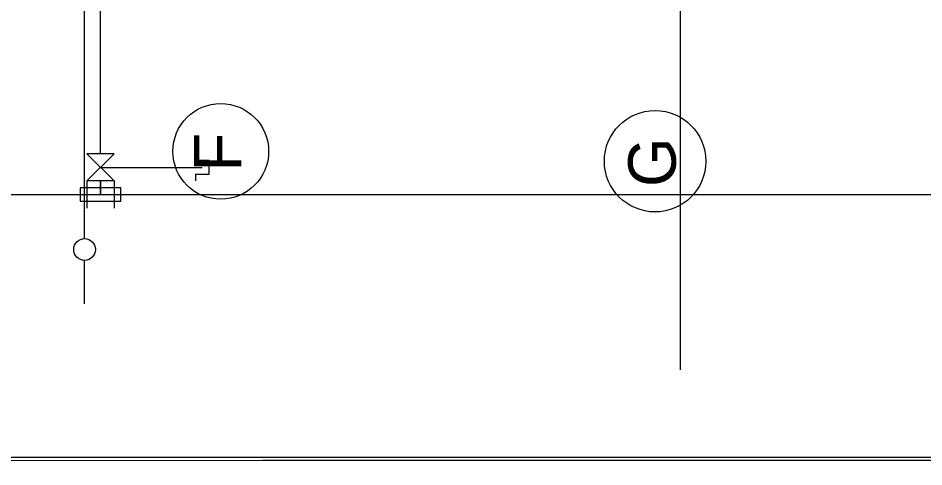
# Model space of a CAD drawing. Extents: x -264205 to -263659, y -1242401 to -1241986.
# Drawn here: x -263888.26 to -263871.58, y -1242255.16 to -1242246.89 of the extents above; entities that cross this region are included whole.
import ezdxf

# ---------------------------------------------------------------- set-up
doc = ezdxf.new("R2010")
doc.units = 0
for name, color, linetype in [('HESCON_OSI_STAVBY_KFA', 7, 'Continuous'), ('PROJEKT_OBRUBNIKY_KOMUNIKACIE', 7, 'Continuous'), ('SITUACIA_DSP_2D', 7, 'Continuous'), ('SO_20-2_OBRUBNIKY_HORNA_HRANA', 7, 'Continuous')]:
    doc.layers.add(name, color=color, linetype=linetype)

msp = doc.modelspace()

# ---------------------------------------------------------------- linework, layer by layer
at = {"layer": 'HESCON_OSI_STAVBY_KFA'}
for centre, radius in [((-263884.528, -1242249.345), 0.882), ((-263876.528, -1242249.526), 0.935)]:
    msp.add_circle(centre, radius, dxfattribs=at)
at = {"layer": 'PROJEKT_OBRUBNIKY_KOMUNIKACIE'}
msp.add_lwpolyline([(-263854.468, -1242263.985), (-263917.08, -1242263.982), (-263901.868, -1242254.982), (-263854.468, -1242254.985), (-263854.468, -1242263.985)], dxfattribs=at)
at = {"layer": 'SITUACIA_DSP_2D'}
for p, q in [((-263887.043, -1242235.757), (-263887.043, -1242250.954)), ((-263886.743, -1242249.39), (-263886.743, -1242235.757)), ((-263876.068, -1242241.132), (-263876.068, -1242253.37)), ((-263886.493, -1242249.39), (-263886.993, -1242249.39)), ((-263886.993, -1242249.89), (-263886.493, -1242249.39)), ((-263886.993, -1242249.39), (-263886.493, -1242249.89)), ((-263884.993, -1242249.515), (-263884.993, -1242249.39)), ((-263884.743, -1242249.515), (-263884.993, -1242249.515)), ((-263884.743, -1242249.765), (-263884.743, -1242249.515)), ((-263886.743, -1242249.64), (-263884.868, -1242249.64)), ((-263884.993, -1242249.765), (-263884.993, -1242249.89)), ((-263884.993, -1242249.765), (-263884.743, -1242249.765)), ((-263886.493, -1242249.89), (-263886.993, -1242249.89)), ((-263886.993, -1242249.89), (-263886.993, -1242250.39)), ((-263886.743, -1242250.14), (-263886.743, -1242249.89)), ((-263886.743, -1242249.89), (-263886.743, -1242250.14)), ((-263886.493, -1242249.89), (-263886.493, -1242250.39)), ((-263886.368, -1242250.015), (-263887.118, -1242250.015)), ((-263887.118, -1242250.015), (-263887.118, -1242250.265)), ((-263886.368, -1242250.265), (-263886.368, -1242250.015)), ((-263924.143, -1242250.14), (-263788.143, -1242250.14)), ((-263887.118, -1242250.265), (-263886.368, -1242250.265)), ((-263887.043, -1242251.353), (-263887.043, -1242252.153)), ((-263901.868, -1242254.982), (-263854.468, -1242254.985))]:
    msp.add_line(p, q, dxfattribs=at)
msp.add_circle((-263887.036, -1242251.153), 0.2, dxfattribs=at)
at = {"layer": 'SO_20-2_OBRUBNIKY_HORNA_HRANA'}
msp.add_lwpolyline([(-263854.465, -1242263.815), (-263854.458, -1242255.02), (-263866.883, -1242255.042), (-263883.752, -1242255.044), (-263902.029, -1242255.047), (-263909.175, -1242255.048), (-263919.956, -1242255.04), (-263920.002, -1242255.04)], dxfattribs=at)

# ---------------------------------------------------------------- texts
at = {"layer": 'HESCON_OSI_STAVBY_KFA'}
for s, p in [('F', (-263884.147, -1242249.718)), ('G', (-263876.147, -1242250.001))]:
    msp.add_text(s, height=0.875, rotation=90, dxfattribs=at).set_placement(p)

doc.saveas('drawing.dxf')
